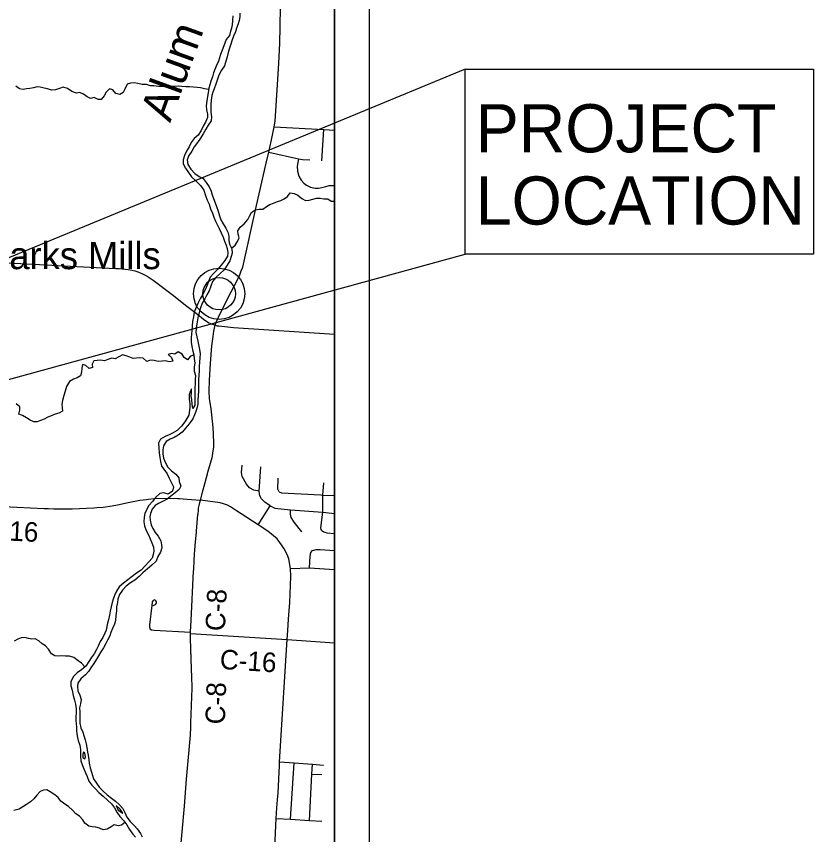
# Model space of a CAD drawing. Extents: x 0 to 34, y 0 to 22.
# Drawn here: x 9.293 to 11.611, y 14.803 to 17.181 of the extents above; entities that cross this region are included whole.
import ezdxf

# ---------------------------------------------------------------- set-up
doc = ezdxf.new("R2010")
doc.units = 0
for name, color, linetype in [('GM_X_City_Street', 7, 'Continuous'), ('GM_X_Corporation', 7, 'Continuous'), ('GM_X_County_Road', 7, 'Continuous'), ('GM_X_County_Road_Text', 7, 'Continuous'), ('GM_X_Major_River', 7, 'Continuous'), ('GM_X_Major_River_Text', 7, 'Continuous'), ('GM_X_Minor_River', 7, 'Continuous'), ('GM_X_Township_Road', 7, 'Continuous'), ('GM_X_Unincorporated', 7, 'Continuous'), ('GM_X_Unincorporated_Location', 7, 'Continuous'), ('GM_X_Unincorporated_Text', 7, 'Continuous'), ('SH_Data', 7, 'Continuous'), ('SH_Text', 7, 'Continuous')]:
    doc.layers.add(name, color=color, linetype=linetype)

msp = doc.modelspace()

# ---------------------------------------------------------------- linework, layer by layer
at = {"layer": 'GM_X_City_Street'}
for p, q in [((10.1813, 16.7614), (10.1866, 16.8522)), ((9.9961, 15.7036), (10.031, 15.7587)), ((10.09, 14.8474), (10.1008, 15.0111)), ((10.1522, 14.9786), (10.1813, 14.9771))]:
    msp.add_line(p, q, dxfattribs=at)
for points in [[(10.0428, 16.8599), (10.1866, 16.8522), (10.2182, 16.8506)], [(10.0265, 16.7866), (10.1133, 16.767), (10.1247, 16.7649), (10.1457, 16.7642)], [(10.1133, 16.767), (10.1094, 16.7453), (10.1101, 16.7307), (10.114, 16.7168), (10.1211, 16.7047), (10.1289, 16.6958), (10.1364, 16.6901), (10.1482, 16.6844), (10.1614, 16.6816), (10.1717, 16.682), (10.1806, 16.6841), (10.1927, 16.6866), (10.2019, 16.6894), (10.2148, 16.6898), (10.2182, 16.6896)], [(9.9986, 15.8009), (9.9834, 15.8036), (9.9703, 15.8103), (9.9622, 15.8211), (9.949, 15.8434), (9.9477, 15.8548), (9.9494, 15.8768)], [(10.031, 15.7587), (10.015, 15.769), (10.0054, 15.7783), (10.0003, 15.7877), (9.9986, 15.8009), (10.0033, 15.8717)], [(10.0568, 15.7993), (10.0535, 15.807), (10.0544, 15.8388)], [(10.1814, 15.6864), (10.1788, 15.6895), (10.1777, 15.6944), (10.1835, 15.7398), (10.1843, 15.7898), (10.1868, 15.8248)], [(10.0568, 15.7993), (10.0636, 15.7962), (10.1779, 15.7901), (10.1843, 15.7898), (10.2182, 15.788)], [(10.031, 15.7587), (10.0445, 15.752), (10.09, 15.7466), (10.1835, 15.7398), (10.2182, 15.7361)], [(10.1228, 15.6828), (10.1005, 15.7105), (10.0917, 15.724), (10.09, 15.7337), (10.09, 15.7466)], [(10.1814, 15.6864), (10.1863, 15.6825), (10.1957, 15.6797), (10.2182, 15.6781)], [(10.1447, 15.5786), (10.1474, 15.6123), (10.1491, 15.6224), (10.1538, 15.6282)], [(10.1538, 15.6282), (10.1649, 15.6315), (10.1757, 15.6319), (10.2182, 15.6283)], [(10.0897, 15.5759), (10.1447, 15.5786), (10.2182, 15.5732)], [(10.0582, 15.0143), (10.1008, 15.0111), (10.1536, 15.0071), (10.1858, 15.0047)], [(10.1453, 14.8439), (10.1522, 14.9786), (10.1536, 15.0071)], [(10.0485, 14.85), (10.09, 14.8474), (10.1453, 14.8439), (10.1805, 14.8416)]]:
    msp.add_lwpolyline(points, dxfattribs=at)
at = {"layer": 'GM_X_Corporation'}
for points in [[(10.2182, 13.9957), (10.2182, 20.0965)], [(8.5129, 13.2965), (10.2182, 13.2965), (10.2182, 17.9339)]]:
    msp.add_lwpolyline(points, dxfattribs=at)
at = {"layer": 'GM_X_County_Road'}
for p, q in [((9.7676, 15.7796), (9.7774, 15.779)), ((9.8856, 15.7668), (9.8278, 15.7748)), ((9.7993, 15.3877), (9.7995, 15.3915)), ((9.7993, 15.3877), (10.0804, 15.3696)), ((10.0804, 15.3696), (10.2182, 15.36))]:
    msp.add_line(p, q, dxfattribs=at)
for points in [[(9.8661, 15.9677), (9.8649, 15.9858), (9.8616, 16.0228), (9.8591, 16.0404), (9.8547, 16.0703), (9.8537, 16.092), (9.8545, 16.1229), (9.8554, 16.1405), (9.8572, 16.1719), (9.8613, 16.2237), (9.8647, 16.2507), (9.8666, 16.2663), (9.8706, 16.2834), (9.8749, 16.2946), (9.8855, 16.317), (9.8949, 16.336), (9.9067, 16.3599), (9.9374, 16.4193), (9.9423, 16.4297), (9.9469, 16.4414), (9.9509, 16.4525), (9.9915, 16.6316), (10.0193, 16.7546), (10.0265, 16.7866), (10.0375, 16.8361), (10.0428, 16.8599), (10.0451, 16.8764), (10.0523, 16.9819), (10.0561, 17.0451), (10.0587, 17.1026), (10.0595, 17.1513), (10.0607, 17.2081)], [(8.9857, 16.4796), (9.0758, 16.4746), (9.2874, 16.4641), (9.4504, 16.4554), (9.5623, 16.4493), (9.5822, 16.4483)], [(9.5822, 16.4483), (9.5921, 16.4478), (9.6093, 16.4463), (9.6177, 16.4452), (9.6282, 16.4432), (9.6378, 16.4411), (9.6488, 16.4373), (9.6616, 16.4319), (9.6735, 16.4256), (9.691, 16.4141), (9.7456, 16.3728), (9.7889, 16.3388)], [(9.7889, 16.3388), (9.8117, 16.3209), (9.8305, 16.3063), (9.8382, 16.3003), (9.8454, 16.2951), (9.8525, 16.2906), (9.8706, 16.2834)], [(9.8706, 16.2834), (9.8762, 16.2819), (9.8819, 16.2811), (9.9238, 16.2765), (10.2182, 16.2574)], [(9.8619, 15.8992), (9.8632, 15.9041), (9.8655, 15.9181), (9.867, 15.9291), (9.8674, 15.9375), (9.8674, 15.9458), (9.8665, 15.9616), (9.8661, 15.9677)], [(9.8485, 15.8512), (9.8498, 15.8561), (9.8575, 15.8828), (9.8619, 15.8992)], [(9.8278, 15.7748), (9.836, 15.805), (9.8485, 15.8512)], [(8.9542, 15.7736), (9.104, 15.7658), (9.215, 15.758), (9.2946, 15.7543), (9.3735, 15.751), (9.3864, 15.7502)], [(9.587, 15.7615), (9.6176, 15.768), (9.6523, 15.7746), (9.6714, 15.7771), (9.6765, 15.7776)], [(9.6765, 15.7776), (9.6949, 15.7795), (9.7325, 15.7806), (9.7626, 15.78), (9.7676, 15.7796)], [(9.7774, 15.779), (9.7893, 15.7782), (9.8278, 15.7748)], [(9.8221, 15.7446), (9.8228, 15.7517), (9.8241, 15.7594), (9.8259, 15.7679), (9.8278, 15.7748)], [(9.3864, 15.7502), (9.4022, 15.7493), (9.4548, 15.7501), (9.5179, 15.7525), (9.5271, 15.7531)], [(9.5271, 15.7531), (9.5454, 15.7545), (9.5712, 15.7582), (9.587, 15.7615)], [(10.0844, 15.4285), (10.0877, 15.4774), (10.0907, 15.5529), (10.0897, 15.5759), (10.0846, 15.6046), (10.0799, 15.617), (10.0715, 15.6329), (10.0637, 15.6454), (10.0509, 15.6626), (10.0241, 15.6847), (9.9961, 15.7036), (9.9296, 15.7459), (9.9158, 15.7552), (9.9064, 15.7606), (9.8954, 15.7644), (9.8856, 15.7668)], [(9.8164, 15.6818), (9.8167, 15.6849), (9.8209, 15.7334)], [(9.8209, 15.7334), (9.821, 15.7344), (9.8211, 15.7354), (9.8221, 15.7446)], [(9.8111, 15.6199), (9.8116, 15.6272), (9.8126, 15.6443), (9.8164, 15.6818)], [(9.8099, 15.5993), (9.8101, 15.6035), (9.8106, 15.6136), (9.8111, 15.6199)], [(9.8083, 15.5681), (9.8086, 15.5733), (9.8087, 15.5743), (9.8099, 15.5993)], [(9.7995, 15.3915), (9.7995, 15.3926), (9.8008, 15.4247), (9.8083, 15.5681)], [(10.0804, 15.3696), (10.0822, 15.3963), (10.0844, 15.4285)], [(9.7996, 15.3674), (9.7995, 15.3774), (9.7993, 15.3877)], [(9.8011, 15.3173), (9.8007, 15.3264), (9.8006, 15.3295), (9.7999, 15.3496), (9.7996, 15.3674)], [(10.0577, 15.004), (10.0582, 15.0143), (10.0804, 15.3696)], [(9.7997, 15.116), (9.7999, 15.123), (9.8001, 15.1281), (9.8036, 15.2281), (9.8031, 15.2636), (9.8024, 15.2817), (9.8011, 15.3173)], [(9.7405, 14.5766), (9.7436, 14.5864), (9.7484, 14.602), (9.7538, 14.6193), (9.7571, 14.6334), (9.76, 14.6489), (9.7641, 14.6948), (9.774, 14.7998), (9.7819, 14.8856), (9.7873, 14.964), (9.7988, 15.0921), (9.7997, 15.116)], [(10.0503, 14.8806), (10.0517, 14.9041), (10.0538, 14.9244), (10.0577, 15.004)], [(10.0352, 14.5921), (10.0428, 14.7226), (10.0485, 14.85), (10.0503, 14.8806)]]:
    msp.add_lwpolyline(points, dxfattribs=at)
at = {"layer": 'GM_X_Major_River'}
for points in [[(9.9226, 17.1828), (9.9214, 17.1691), (9.9206, 17.1569), (9.9186, 17.1471), (9.9156, 17.1376), (9.9125, 17.1258), (9.9033, 17.1134), (9.8987, 17.1035), (9.8941, 17.0906), (9.8899, 17.0804), (9.8864, 17.0705), (9.8837, 17.0603), (9.8802, 17.0508), (9.8737, 17.0364), (9.8695, 17.0266), (9.8657, 17.0171), (9.8629, 17.0057), (9.8587, 16.9928), (9.8556, 16.9822), (9.8525, 16.9724), (9.8502, 16.9591), (9.8486, 16.9481), (9.8467, 16.9352), (9.8451, 16.9208), (9.8454, 16.9094), (9.8484, 16.8964), (9.8483, 16.8869), (9.8426, 16.8733), (9.8361, 16.8616), (9.8303, 16.8491), (9.8219, 16.8354), (9.8101, 16.8256), (9.8013, 16.8143), (9.7956, 16.8018), (9.7875, 16.7893), (9.7814, 16.7764), (9.7775, 16.7639), (9.7775, 16.7521), (9.7842, 16.7396), (9.7933, 16.7277), (9.8023, 16.7148), (9.8155, 16.7018), (9.828, 16.6892), (9.8378, 16.6755), (9.8423, 16.6607), (9.8479, 16.6466), (9.8531, 16.6356), (9.8576, 16.6219), (9.8636, 16.6093), (9.867, 16.5975)], [(9.9424, 17.1903), (9.9427, 17.1796), (9.9411, 17.1686), (9.9377, 17.1591), (9.9327, 17.1463), (9.9296, 17.1364), (9.9242, 17.1231), (9.9204, 17.1129), (9.9165, 17.1004), (9.9123, 17.0886), (9.9084, 17.0757), (9.9053, 17.0636), (9.8976, 17.0371), (9.8896, 17.0246), (9.8816, 17.0106), (9.8773, 16.9984), (9.8731, 16.9844), (9.8677, 16.9704), (9.8639, 16.9605), (9.8608, 16.9507), (9.8592, 16.9378), (9.8584, 16.9252), (9.8579, 16.9158), (9.8586, 16.9025), (9.8601, 16.8892), (9.8593, 16.8774), (9.8505, 16.8649), (9.8436, 16.8532), (9.8356, 16.8399), (9.8279, 16.8271), (9.8199, 16.8146), (9.81, 16.8017), (9.8031, 16.7888), (9.7939, 16.7763), (9.7893, 16.7642), (9.7911, 16.7505), (9.8005, 16.7372), (9.8115, 16.7246), (9.8243, 16.7158), (9.8361, 16.7101), (9.8451, 16.6986), (9.853, 16.6857), (9.859, 16.6731), (9.8624, 16.6621), (9.8661, 16.6515), (9.871, 16.6389), (9.8747, 16.6283), (9.8796, 16.6153), (9.8833, 16.6013), (9.8878, 16.5895), (9.8938, 16.5777), (9.9017, 16.5655), (9.9077, 16.5537), (9.9107, 16.5423), (9.9107, 16.5294), (9.9121, 16.5187), (9.9196, 16.5058), (9.92, 16.4929), (9.9172, 16.483), (9.9134, 16.4709), (9.9061, 16.4576), (9.897, 16.4444), (9.8848, 16.4327), (9.873, 16.4221), (9.863, 16.41), (9.8584, 16.3971), (9.853, 16.3835)], [(9.867, 16.5975), (9.8719, 16.5861), (9.8828, 16.5641), (9.8884, 16.5515), (9.8944, 16.5393), (9.8977, 16.5275), (9.9026, 16.5157), (9.9056, 16.5062), (9.9074, 16.4937), (9.9066, 16.4838), (9.8986, 16.4713), (9.8883, 16.4577), (9.8784, 16.4464), (9.8669, 16.4347), (9.8559, 16.4233), (9.8517, 16.4108), (9.8474, 16.4002), (9.8421, 16.3866), (9.8355, 16.3737), (9.8283, 16.3623), (9.8214, 16.3483), (9.816, 16.3362), (9.8102, 16.321), (9.8075, 16.3074), (9.8052, 16.2941), (9.8036, 16.2812), (9.8028, 16.2683), (9.8024, 16.2577), (9.8015, 16.2478), (9.8015, 16.2341), (9.8029, 16.2212), (9.8055, 16.2079), (9.8085, 16.1977), (9.8103, 16.1866), (9.8122, 16.1733), (9.8099, 16.1627), (9.8098, 16.1498), (9.8135, 16.1373), (9.8123, 16.1247), (9.8123, 16.1134), (9.8118, 16.1012), (9.8118, 16.0875), (9.8113, 16.0746), (9.8116, 16.0632), (9.8116, 16.0507), (9.8062, 16.0409), (9.8044, 16.0542), (9.8026, 16.0671), (9.8015, 16.077), (9.8019, 16.0864), (9.8019, 16.0982), (9.7979, 16.091), (9.7952, 16.0809), (9.795, 16.0686), (9.7968, 16.0553), (9.7971, 16.0455), (9.7967, 16.036), (9.794, 16.0223), (9.7882, 16.0121), (9.7825, 16.0023), (9.773, 15.9898), (9.7604, 15.9773), (9.7471, 15.9698), (9.7372, 15.9649), (9.7254, 15.96), (9.7121, 15.9525), (9.7064, 15.9407), (9.7067, 15.9263), (9.7077, 15.9126), (9.7096, 15.899), (9.7118, 15.8872), (9.7151, 15.8735), (9.7249, 15.8609), (9.7309, 15.8514), (9.737, 15.8388), (9.7441, 15.8255), (9.7497, 15.8137), (9.7466, 15.8008), (9.7344, 15.7918), (9.7216, 15.796), (9.7098, 15.7942), (9.6976, 15.7825), (9.6888, 15.7707), (9.6778, 15.759), (9.6709, 15.7469), (9.6663, 15.7363), (9.6643, 15.7257), (9.6635, 15.712), (9.6657, 15.6998), (9.6702, 15.6862), (9.677, 15.6736), (9.6822, 15.6622), (9.6867, 15.6512), (9.6916, 15.6382), (9.6927, 15.6264), (9.6904, 15.617), (9.688, 15.6067), (9.6777, 15.5954), (9.6671, 15.5844), (9.656, 15.5716), (9.6423, 15.5625)], [(9.853, 16.3835), (9.8462, 16.3714), (9.8404, 16.3604), (9.8331, 16.3471), (9.8285, 16.3339), (9.8254, 16.3244), (9.823, 16.3156)], [(9.823, 16.3156), (9.8216, 16.3107), (9.8192, 16.2986), (9.8173, 16.2872), (9.8153, 16.2743), (9.8149, 16.2618), (9.8175, 16.2492), (9.8205, 16.2367), (9.8238, 16.2226), (9.8253, 16.2131), (9.8275, 16.2006), (9.8267, 16.1881), (9.8255, 16.1759), (9.8246, 16.163), (9.8242, 16.1505), (9.823, 16.138), (9.8222, 16.1251), (9.822, 16.0913), (9.8216, 16.0788), (9.8208, 16.0666), (9.8203, 16.0548), (9.8188, 16.045), (9.8145, 16.0329), (9.8107, 16.0226), (9.8057, 16.0109), (9.795, 15.9969), (9.7855, 15.9848), (9.7752, 15.9723), (9.7637, 15.964), (9.7519, 15.9568), (9.7405, 15.952), (9.7284, 15.9452), (9.7203, 15.9331), (9.7184, 15.9213), (9.7183, 15.9092), (9.7202, 15.897), (9.7262, 15.8837), (9.7337, 15.8707), (9.7439, 15.8597), (9.7567, 15.8505), (9.765, 15.8402), (9.7665, 15.8288), (9.7706, 15.8159), (9.766, 15.8057), (9.755, 15.7962), (9.7424, 15.786), (9.731, 15.7781), (9.7177, 15.7706), (9.7059, 15.765), (9.6964, 15.7593), (9.6876, 15.7487), (9.683, 15.7362), (9.6814, 15.7263), (9.6817, 15.7165), (9.6847, 15.7028), (9.6892, 15.6929), (9.696, 15.6807), (9.7054, 15.67), (9.7129, 15.6571), (9.7151, 15.6453), (9.7155, 15.6358), (9.7116, 15.6237), (9.7044, 15.6112), (9.699, 15.5979), (9.6864, 15.5859), (9.6746, 15.5753), (9.6605, 15.5636), (9.6498, 15.553), (9.6376, 15.5424), (9.6251, 15.5345), (9.6121, 15.5247), (9.6018, 15.5134), (9.5931, 15.5009), (9.5884, 15.4869), (9.5869, 15.477), (9.5845, 15.4652), (9.5837, 15.4527), (9.5825, 15.4398), (9.5809, 15.425), (9.5782, 15.4148), (9.5725, 15.4019), (9.5675, 15.3901), (9.5644, 15.3803), (9.5583, 15.3682), (9.5529, 15.3583), (9.546, 15.3458), (9.5388, 15.3337), (9.5315, 15.3224), (9.5258, 15.3125), (9.5185, 15.3004), (9.5116, 15.2906), (9.5028, 15.2769), (9.4937, 15.2671), (9.48, 15.2558), (9.4719, 15.2433), (9.4711, 15.2338), (9.4718, 15.2209), (9.4771, 15.208), (9.4816, 15.1958), (9.4796, 15.1833), (9.4769, 15.1711)], [(9.6423, 15.5625), (9.6294, 15.5531), (9.6168, 15.5433), (9.6046, 15.5335), (9.5917, 15.5229), (9.5836, 15.5104), (9.5783, 15.4975), (9.5744, 15.4873), (9.5713, 15.4778), (9.5659, 15.452), (9.5636, 15.4407), (9.5605, 15.4274), (9.5581, 15.4171), (9.5542, 15.3974), (9.5504, 15.3879), (9.5439, 15.3754), (9.537, 15.3637), (9.5305, 15.3505), (9.5259, 15.3406), (9.519, 15.3285), (9.5106, 15.3164), (9.5034, 15.3062), (9.4946, 15.2925), (9.4824, 15.282), (9.4698, 15.2729), (9.458, 15.2612), (9.4511, 15.2472), (9.4514, 15.2347), (9.4548, 15.2221), (9.4585, 15.2073), (9.4615, 15.1936), (9.4644, 15.1815), (9.467, 15.1682), (9.4666, 15.1575), (9.4658, 15.1442), (9.4657, 15.1348), (9.4668, 15.1249), (9.4679, 15.115), (9.4682, 15.1051), (9.4689, 15.0953), (9.4704, 15.0854), (9.473, 15.0759), (9.4771, 15.0629), (9.4797, 15.05), (9.4796, 15.0303), (9.4807, 15.0174), (9.4852, 15.0037), (9.4893, 14.9942), (9.4938, 14.982), (9.4983, 14.9717), (9.5039, 14.9584), (9.5122, 14.9462), (9.5224, 14.9367)], [(9.4769, 15.1711), (9.4772, 15.1598), (9.4776, 15.1499), (9.4771, 15.1393), (9.4771, 15.1267), (9.4808, 15.113), (9.486, 15.1009), (9.489, 15.091), (9.4931, 15.0784), (9.4957, 15.0663), (9.4976, 15.0564), (9.4998, 15.0427), (9.5013, 15.0332), (9.5035, 15.0199), (9.5049, 15.0104), (9.5072, 14.9971), (9.5109, 14.9846), (9.5139, 14.9743), (9.5172, 14.9648), (9.5255, 14.9519), (9.5349, 14.94), (9.5455, 14.929), (9.5565, 14.9183), (9.5693, 14.9088), (9.581, 14.9003), (9.5931, 14.8897), (9.6025, 14.8782), (9.6085, 14.8668), (9.6145, 14.8539), (9.624, 14.8409), (9.636, 14.8287), (9.6443, 14.8192), (9.6538, 14.8062), (9.6586, 14.7963)], [(9.4884, 15.0428), (9.4857, 15.0356), (9.4864, 15.0257), (9.4921, 15.023)], [(9.4921, 15.023), (9.4944, 15.0291), (9.4918, 15.039), (9.4884, 15.0428)], [(9.5224, 14.9367), (9.523, 14.9361), (9.533, 14.9252), (9.5451, 14.9142), (9.5575, 14.9027), (9.5692, 14.892), (9.5783, 14.8806), (9.585, 14.8677), (9.5941, 14.8555), (9.605, 14.8429), (9.6137, 14.8307), (9.6223, 14.8174), (9.6318, 14.8044), (9.6397, 14.7949)], [(9.5829, 14.8874), (9.5885, 14.8741), (9.6021, 14.8653)], [(9.6021, 14.8653), (9.5946, 14.8767), (9.5829, 14.8874)]]:
    msp.add_lwpolyline(points, dxfattribs=at)
at = {"layer": 'GM_X_Minor_River'}
for points in [[(9.8519, 16.9685), (9.8403, 16.9708), (9.8286, 16.9732), (9.8184, 16.9744), (9.8078, 16.9756), (9.796, 16.9758), (9.7858, 16.9762), (9.7744, 16.9771), (9.7642, 16.9783), (9.7536, 16.9773), (9.743, 16.977), (9.7316, 16.9775), (9.7187, 16.9772), (9.7062, 16.977), (9.693, 16.979), (9.6831, 16.9791), (9.6714, 16.9834), (9.6585, 16.9835), (9.646, 16.9863), (9.6351, 16.9883), (9.6244, 16.9865), (9.6149, 16.9843), (9.6084, 16.9699), (9.6034, 16.9593), (9.5935, 16.9541), (9.5825, 16.9565), (9.5735, 16.9672), (9.5637, 16.9707), (9.5541, 16.9606), (9.5483, 16.9504), (9.5399, 16.9398), (9.5304, 16.9395), (9.5195, 16.9453), (9.5088, 16.9424), (9.499, 16.9474), (9.4877, 16.9551), (9.4775, 16.9598), (9.4677, 16.9576), (9.4544, 16.963), (9.4413, 16.9715), (9.4288, 16.9754), (9.4185, 16.9713), (9.4071, 16.9677), (9.3954, 16.967), (9.3833, 16.9705), (9.3734, 16.9725), (9.3625, 16.9753), (9.353, 16.9758), (9.3424, 16.9736), (9.3321, 16.9718), (9.3226, 16.9707), (9.3124, 16.9685), (9.3021, 16.9705), (9.2916, 16.9782)], [(9.9187, 16.5074), (9.9291, 16.5165), (9.936, 16.5267), (9.9406, 16.5373), (9.9377, 16.5483), (9.9363, 16.5578), (9.9439, 16.5688), (9.955, 16.5785), (9.9654, 16.5902), (9.9707, 16.6), (9.9765, 16.6106), (9.9876, 16.6192), (9.9986, 16.6207), (10.0096, 16.6206), (10.0203, 16.6284), (10.0298, 16.6344), (10.0404, 16.6381), (10.0519, 16.6429), (10.0614, 16.6459), (10.0716, 16.6503), (10.0812, 16.6575), (10.0889, 16.6684), (10.1006, 16.6664), (10.1111, 16.661), (10.1224, 16.6521), (10.1334, 16.6456), (10.1444, 16.6466), (10.1546, 16.6496), (10.1653, 16.6529), (10.1759, 16.6528), (10.1872, 16.6508), (10.1986, 16.651), (10.2084, 16.6441), (10.2182, 16.6443)], [(9.8086, 16.1969), (9.7984, 16.1927), (9.7907, 16.1825), (9.7809, 16.1898), (9.7746, 16.1994), (9.7637, 16.2063), (9.7541, 16.1988), (9.7443, 16.2016), (9.7344, 16.1982), (9.7442, 16.1898), (9.7482, 16.1787), (9.7369, 16.1766), (9.7259, 16.1797), (9.7164, 16.179), (9.7054, 16.1776), (9.6937, 16.1812), (9.6816, 16.1816), (9.6721, 16.1779), (9.6615, 16.1875), (9.6517, 16.1884), (9.6422, 16.1877), (9.6324, 16.187), (9.6225, 16.1906), (9.6123, 16.1941), (9.6014, 16.1972), (9.5911, 16.1912), (9.58, 16.1856), (9.5702, 16.1876), (9.5592, 16.1836), (9.5489, 16.1799), (9.5379, 16.1815), (9.5277, 16.1808), (9.5182, 16.1802), (9.5136, 16.1703), (9.5139, 16.1605), (9.5044, 16.1571), (9.4946, 16.1663), (9.4848, 16.1687), (9.4831, 16.1581), (9.4827, 16.1467), (9.4792, 16.1365), (9.4696, 16.1301), (9.4586, 16.1268), (9.4479, 16.1197), (9.4391, 16.105), (9.4352, 16.0921), (9.4305, 16.0792), (9.4273, 16.0641), (9.425, 16.0542), (9.426, 16.044), (9.4267, 16.0337), (9.4164, 16.0277), (9.4061, 16.0252), (9.3966, 16.0214), (9.3848, 16.0162), (9.3742, 16.0106), (9.3635, 16.0066), (9.3536, 16.0021), (9.3434, 16.0022), (9.3328, 16.0076), (9.3223, 16.0138), (9.311, 16.0207), (9.3, 16.0246), (9.3035, 16.036), (9.3029, 16.0466), (9.2927, 16.0551)], [(9.492, 15.2903), (9.4826, 15.3014), (9.4724, 15.308), (9.46, 15.318), (9.4475, 15.3215), (9.4362, 15.3216), (9.4256, 15.3225), (9.4161, 15.3211), (9.4047, 15.3227), (9.3949, 15.3277), (9.3859, 15.3415), (9.3781, 15.3518), (9.3683, 15.3572), (9.3585, 15.3664), (9.3479, 15.3718), (9.3381, 15.3708), (9.3279, 15.3732), (9.3173, 15.3752), (9.3074, 15.3745), (9.2968, 15.3712), (9.2869, 15.3652)], [(9.6083, 14.8383), (9.5981, 14.8299), (9.5886, 14.8281), (9.5777, 14.8316), (9.5681, 14.8252), (9.5571, 14.8189), (9.5457, 14.8163), (9.5347, 14.8214), (9.5242, 14.8245), (9.5136, 14.8254), (9.5037, 14.8277), (9.492, 14.8358), (9.4865, 14.8457), (9.4763, 14.8565), (9.4658, 14.863), (9.4564, 14.8738), (9.4444, 14.8849), (9.4334, 14.8911), (9.4221, 14.8999), (9.4143, 14.911), (9.4045, 14.9183), (9.3917, 14.9268), (9.3815, 14.9326), (9.3716, 14.9319), (9.3621, 14.9282), (9.3522, 14.9173), (9.3434, 14.9067), (9.3338, 14.8981), (9.3224, 14.8906), (9.3121, 14.8835), (9.301, 14.8771), (9.2855, 14.8727)]]:
    msp.add_lwpolyline(points, dxfattribs=at)
at = {"layer": 'GM_X_Township_Road'}
msp.add_lwpolyline([(9.6902, 15.469), (9.6971, 15.4717), (9.7006, 15.4757), (9.7006, 15.4798), (9.6988, 15.4825), (9.6952, 15.4851), (9.6909, 15.4835), (9.6879, 15.4794), (9.687, 15.4682), (9.6799, 15.4129), (9.6797, 15.4072), (9.6813, 15.4013), (9.6857, 15.3979), (9.6936, 15.397), (9.7995, 15.3915)], dxfattribs=at)
at = {"layer": 'GM_X_Unincorporated'}
for radius in [0.0744, 0.0472]:
    msp.add_circle((9.8824, 16.3748), radius, dxfattribs=at)
at = {"layer": 'GM_X_Unincorporated_Location'}
msp.add_line((9.8824, 16.3748), (9.8824, 16.3748), dxfattribs=at)
at = {"layer": 'SH_Data'}
for p, q in [((10.3182, 20.1965), (10.3182, 13.1965)), ((10.2182, 20.0965), (10.2182, 13.2965))]:
    msp.add_line(p, q, dxfattribs=at)
at = {"layer": 'SH_Text'}
for points in [[(10.5973, 17.0279), (6.7238, 15.4274), (10.5973, 16.4895)], [(10.5973, 17.0279), (11.6106, 17.0279), (11.6106, 16.4895), (10.5973, 16.4895)]]:
    msp.add_lwpolyline(points, close=True, dxfattribs=at)

# ---------------------------------------------------------------- texts
at = {"layer": 'GM_X_County_Road_Text'}
for s, rotation, p in [('C-16', 357.2584, (9.1912, 15.6611)), ('C-8', 87.2893, (9.899, 15.3932)), ('C-16', 356.3107, (9.883, 15.2846)), ('C-8', 88.1425, (9.899, 15.1225))]:
    msp.add_text(s, height=0.05682, rotation=rotation, dxfattribs=at).set_placement(p)
at = {"layer": 'GM_X_Major_River_Text'}
msp.add_text('Alum', height=0.0947, rotation=69.9993, dxfattribs=at).set_placement((9.74, 16.8703))
at = {"layer": 'GM_X_Unincorporated_Text'}
msp.add_text('Parks Mills', height=0.078977, rotation=0, dxfattribs=at).set_placement((9.202, 16.4463))
at = {"layer": 'SH_Text'}
for s, p in [('PROJECT ', (10.6286, 16.7858)), ('LOCATION', (10.6286, 16.5758))]:
    msp.add_text(s, height=0.14, dxfattribs=at).set_placement(p)

doc.saveas('drawing.dxf')
